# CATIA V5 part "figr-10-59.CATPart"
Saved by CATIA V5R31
Part number: Part1
Bounding box of the stored display mesh (mm): x -322.306 to 0, y -118.205 to 88.531, z 0 to 101.949
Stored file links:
  D:\PROJECTS\Project 2021\US EDITION\CATIA V5 6R 2021\Resources\Part Files\c10_catia_v5_6r2021_prt\c10_catia_v5_6r2021_prt\figr-10-59.CATPart
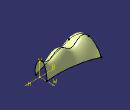
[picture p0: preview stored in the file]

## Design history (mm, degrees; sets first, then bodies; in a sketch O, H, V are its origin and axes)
Set1
  Curve1: Elements (vertex of Sketch2; vertex of Sketch1; vertex of Sketch3)
  Curve2: Elements (Sketch2.P2; vertex of Sketch1; Sketch3.P2)
  Loft1: Sections (Curve2; Sketch4), Guides (Sketch2; Sketch1; Sketch3)
Body1 (main body)
  Sketch1 on zx-plane, origin (0, 0, 0), H (-1, 0, 0), V (0, 0, 1)
    spline S1 through (0, 96.336) (70.1946, 72.4244) (144.1119, 96.336) (203.5098, 63.985) (253.668, 92.1163) (322.3056, 72.4244)
    point P1 (0, 96.336)
    coincidence: P1 V
  Sketch2 on xy-plane, origin (0, 0, 0), H (1, 0, 0), V (0, 1, 0)
    point P1 (0, 47.0553)
    point P2 (-315.9706, 88.5306)
    arc A1 centre (-78.7604, 671.3501) radius 629.2433 from (0, 47.0553) to (-315.9706, 88.5306) cw
    coincidence: P1 V
  Sketch3 on xy-plane, origin (0, 0, 0), H (1, 0, 0), V (0, 1, 0)
    line L1 (0, -26.5991) -> (-311.8959, -118.2048)
    point P1 (0, -26.5991)
    point P2 (-311.8959, -118.2048)
    coincidence: P1 V
  Sketch4 on yz-plane, origin (0, 0, 0), H (0, 1, 0), V (0, 0, 1)
    point P1 (-26.5991, 0)
    point P2 (0, 58.544)
    point P3 (47.0553, 0)
    reference projected point E1 (47.0553, 0) from vertex of Sketch2
    reference projected point E2 (-26.5991, 0) from vertex of Sketch3
    spline S1 through (-26.5991, 0) (-29.9268, 35.6209) (0, 96.336) (47.0553, 0)
    reference projected point E3 (0, 96.336) from vertex of Sketch1
    point P4 (-26.5991, 0)
    point P5 (0, 96.336)
    point P6 (47.0553, 0)
    coincidence: P1 H, P3 H, E1 P3, P1 E2, P4 P1, P5 V, P6 P3, E3 S1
